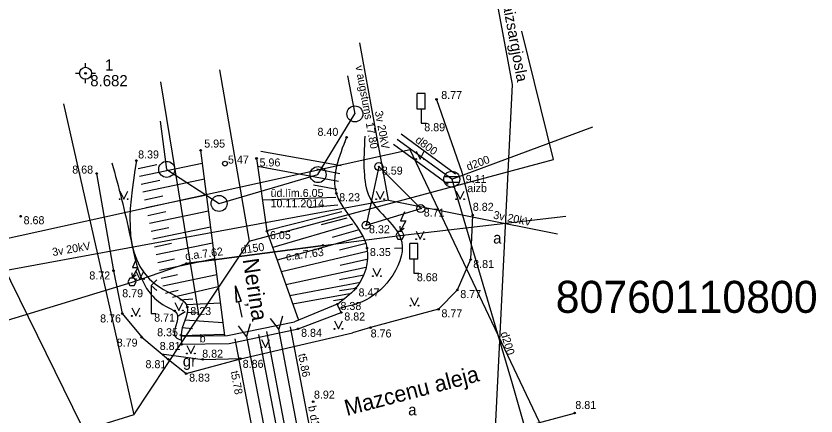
# Model space of a CAD drawing. Extents: x 496078 to 496285, y 304225 to 304369.
# Drawn here: x 496157.26 to 496207.22, y 304311.46 to 304336.44 of the extents above; entities that cross this region are included whole.
import ezdxf

# ---------------------------------------------------------------- set-up
doc = ezdxf.new("R2010")
doc.units = 0
for name, color, linetype in [('APGR_AIZS_####_####_#', 7, 'Continuous'), ('APGR_AIZS_####_TKST_#', 7, 'Continuous'), ('APGR_ELEM_####_####_#', 7, 'Continuous'), ('APGR_SARK_####_####_#', 7, 'Continuous'), ('BUVE_BDET_####_####_#', 7, 'Continuous'), ('BUVE_BDET_####_TKST_#', 7, 'Continuous'), ('CELI_CMAL_####_####_#', 7, 'Continuous'), ('CELI_CSEG_####_TKST_#', 7, 'Continuous'), ('CELI_ELEM_####_####_#', 7, 'Continuous'), ('CELI_IELA_####_TKST_#', 7, 'Continuous'), ('CKOM_ELEM_####_####_#', 7, 'Continuous'), ('ELEK_ACRL_####_####_#', 7, 'Continuous'), ('ELEK_ACRL_####_TKST_#', 7, 'Continuous'), ('ELEK_ELEM_####_####_#', 7, 'Continuous'), ('ELEK_SAVL_####_####_#', 7, 'Continuous'), ('ELEK_VADP_VSPR_####_#', 7, 'Continuous'), ('ELEK_VADV_VSPR_####_#', 7, 'Continuous'), ('ELEK_VADV_VSPR_TKST_#', 7, 'Continuous'), ('GEOD_ELEM_####_####_#', 7, 'Continuous'), ('GEOD_ELEM_####_TKST_#', 7, 'Continuous'), ('HIDG_AATZ_####_TKST_#', 7, 'Continuous'), ('HIDG_ELEM_####_####_#', 7, 'Continuous'), ('HIDG_HNOS_####_TKST_#', 7, 'Continuous'), ('HIDG_PLIN_####_####_#', 7, 'Continuous'), ('HIDG_UATZ_####_TKST_#', 7, 'Continuous'), ('HIDT_CAUR_####_####_#', 7, 'Continuous'), ('HIDT_CAUR_####_TKST_#', 7, 'Continuous'), ('HIDT_CAUR_KONT_####_#', 7, 'Continuous'), ('HIDT_ELEM_####_####_#', 7, 'Continuous'), ('Level 13', 7, 'Continuous'), ('Level 21', 7, 'Continuous'), ('Level 24', 7, 'Continuous'), ('Level 25', 7, 'Continuous'), ('Level 59', 7, 'Continuous'), ('LKAN_ELEM_####_####_#', 7, 'Continuous'), ('LKAN_ELEM_PAST_TKST_#', 7, 'Continuous'), ('LKAN_VADP_PAST_####_#', 7, 'Continuous'), ('LKAN_VADP_PAST_KONT_#', 7, 'Continuous'), ('LKAN_VADP_PAST_TKST_#', 7, 'Continuous'), ('RAMI_UZMR_####_####_#', 7, 'Continuous'), ('RELJ_AATZ_####_TKST_#', 7, 'Continuous'), ('RELJ_ELEM_####_####_#', 7, 'Continuous'), ('RELJ_HORZ_PAMT_####_#', 7, 'Continuous'), ('RELJ_NOGA_####_####_#', 7, 'Continuous'), ('TERT_ELEM_####_####_#', 7, 'Continuous')]:
    doc.layers.add(name, color=color, linetype=linetype)

msp = doc.modelspace()

# ---------------------------------------------------------------- linework, layer by layer
at = {"layer": 'APGR_AIZS_####_####_#'}
msp.add_line((496188.252, 304332.153), (496186.624, 304299.798), dxfattribs=at)
for points in [[(496186.433, 304341.916), (496188.252, 304332.153)], [(496171.482, 304276.481), (496169.303, 304289.245), (496168.626, 304293.523), (496167.995, 304297.351), (496154.713, 304324.372)]]:
    msp.add_lwpolyline(points, dxfattribs=at)
at = {"layer": 'APGR_ELEM_####_####_#'}
for centre in [(496178.42, 304330.32), (496166.67, 304326.86), (496176.12, 304326.53), (496169.94, 304324.73)]:
    msp.add_circle(centre, 0.5, dxfattribs=at)
at = {"layer": 'APGR_SARK_####_####_#'}
for p, q in [((496177.959, 304332.699), (496178.421, 304330.321)), ((496176.116, 304326.534), (496178.421, 304330.321)), ((496166.672, 304326.86), (496166.274, 304329.87)), ((496166.672, 304326.86), (496169.944, 304324.729)), ((496169.944, 304324.729), (496176.116, 304326.534))]:
    msp.add_line(p, q, dxfattribs=at)
at = {"layer": 'BUVE_BDET_####_####_#'}
for points in [[(496167.569, 304316.447), (496167.6, 304315.934), (496170.565, 304315.99), (496174.875, 304316.902), (496177.575, 304317.921), (496177.325, 304318.44), (496174.655, 304317.348)], [(496167.569, 304316.447), (496170.464, 304316.488), (496174.655, 304317.348)]]:
    msp.add_lwpolyline(points, dxfattribs=at)
at = {"layer": 'CELI_CMAL_####_####_#'}
for points in [[(496183.519, 304331.229), (496185.092, 304326.679), (496185.774, 304324.002), (496185.651, 304321.229), (496184.818, 304319.321), (496183.643, 304318.119), (496179.393, 304316.978), (496178.268, 304316.647)], [(496162.292, 304326.6), (496163.347, 304320.532), (496163.898, 304317.856), (496165.111, 304316.377), (496166.772, 304314.993), (496167.885, 304314.104), (496171.28, 304315.033), (496178.268, 304316.647)], [(496166.349, 304315.345), (496168.919, 304314.992), (496171.334, 304315.048)], [(496169.864, 304303.13), (496168.559, 304302.187), (496166.548, 304301.675), (496165.812, 304304.226), (496169.3, 304305.578), (496176.443, 304307.431), (496192.141, 304311.641)]]:
    msp.add_lwpolyline(points, dxfattribs=at)
at = {"layer": 'CELI_ELEM_####_####_#'}
for p, q in [((496182.815, 304331.588), (496182.315, 304331.588)), ((496182.315, 304330.619), (496182.315, 304331.588)), ((496182.815, 304330.619), (496182.815, 304331.588)), ((496182.815, 304330.619), (496182.315, 304330.619)), ((496182.569, 304330.619), (496182.569, 304329.741)), ((496182.569, 304329.741), (496182.884, 304329.741)), ((496182.351, 304322.221), (496181.851, 304322.221)), ((496181.851, 304321.252), (496181.851, 304322.221)), ((496182.351, 304321.252), (496182.351, 304322.221)), ((496182.351, 304321.252), (496181.851, 304321.252)), ((496182.105, 304321.252), (496182.105, 304320.374)), ((496182.105, 304320.374), (496182.42, 304320.374))]:
    msp.add_line(p, q, dxfattribs=at)
for points in [[(496166.044, 304319.96), (496165.702, 304319.604), (496166.058, 304319.305)], [(496165.702, 304319.604), (496165.702, 304317.852), (496166.001, 304317.852)]]:
    msp.add_lwpolyline(points, dxfattribs=at)
at = {"layer": 'CKOM_ELEM_####_####_#'}
for p, q in [((496181.263, 304323.039), (496181.504, 304323.178)), ((496164.53, 304320.135), (496164.771, 304320.274))]:
    msp.add_line(p, q, dxfattribs=at)
for points in [[(496181.512, 304324.201), (496181.263, 304323.638), (496181.599, 304323.638), (496181.263, 304323.039), (496181.241, 304323.309)], [(496164.779, 304321.297), (496164.53, 304320.734), (496164.866, 304320.734), (496164.53, 304320.135), (496164.508, 304320.405)]]:
    msp.add_lwpolyline(points, dxfattribs=at)
for points in [[(496181.107, 304322.509), (496181.373, 304322.509), (496181.506, 304322.739), (496181.373, 304322.97), (496181.107, 304322.97), (496180.974, 304322.739)], [(496164.374, 304319.605), (496164.64, 304319.605), (496164.773, 304319.835), (496164.64, 304320.066), (496164.374, 304320.066), (496164.241, 304319.835)]]:
    msp.add_lwpolyline(points, close=True, dxfattribs=at)
at = {"layer": 'ELEK_ACRL_####_####_#'}
msp.add_line((496176.431, 304322.113), (496167.892, 304320.979), dxfattribs=at)
at = {"layer": 'ELEK_ELEM_####_####_#'}
for centre, radius in [((496179.92, 304327.031), 0.25), ((496179.92, 304327.031), 0.0225), ((496182.535, 304324.415), 0.25), ((496182.535, 304324.415), 0.0225), ((496179.117, 304323.37), 0.25), ((496179.117, 304323.37), 0.0225)]:
    msp.add_circle(centre, radius, dxfattribs=at)
at = {"layer": 'ELEK_SAVL_####_####_#'}
for p, q in [((496179.92, 304327.031), (496179.117, 304323.37)), ((496182.535, 304324.415), (496179.92, 304327.031)), ((496179.117, 304323.37), (496182.535, 304324.415))]:
    msp.add_line(p, q, dxfattribs=at)
at = {"layer": 'ELEK_VADP_VSPR_####_#'}
msp.add_lwpolyline([(496127.411, 304308.505), (496164.51, 304319.823), (496167.892, 304320.979), (496176.431, 304322.113), (496181.231, 304322.724), (496191.596, 304323.927)], dxfattribs=at)
at = {"layer": 'ELEK_VADV_VSPR_####_#'}
for q in [(496178.731, 304334.752), (496133.06, 304316.215), (496191.07, 304322.83)]:
    msp.add_line((496180.524, 304324.939), q, dxfattribs=at)
at = {"layer": 'GEOD_ELEM_####_####_#'}
for p, q in [((496161.602, 304333.233), (496161.602, 304333.483)), ((496160.977, 304332.858), (496161.227, 304332.858)), ((496161.977, 304332.858), (496162.227, 304332.858)), ((496161.602, 304332.233), (496161.602, 304332.483))]:
    msp.add_line(p, q, dxfattribs=at)
for radius in [0.375, 0.05]:
    msp.add_circle((496161.602, 304332.858), radius, dxfattribs=at)
at = {"layer": 'HIDG_ELEM_####_####_#'}
for p, q in [((496170.958, 304319.584), (496171.312, 304318.637)), ((496171.019, 304318.574), (496170.958, 304319.584)), ((496171.312, 304318.637), (496171.019, 304318.574)), ((496171.373, 304317.627), (496171.166, 304318.605))]:
    msp.add_line(p, q, dxfattribs=at)
msp.add_lwpolyline([(496171.166, 304318.605), (496171.312, 304318.637), (496170.958, 304319.584), (496171.019, 304318.574), (496171.166, 304318.605)], dxfattribs=at)
msp.add_circle((496170.312, 304327.219), 0.15, dxfattribs=at)
at = {"layer": 'HIDG_PLIN_####_####_#'}
msp.add_line((496168.79, 304328.047), (496170.285, 304316.485), dxfattribs=at)
msp.add_lwpolyline([(496172.28, 304327.542), (496172.931, 304323.003), (496174.901, 304317.448)], dxfattribs=at)
at = {"layer": 'HIDT_CAUR_####_####_#'}
for p, q in [((496175.928, 304304.99), (496173.664, 304316.879)), ((496171.657, 304316.413), (496173.961, 304304.517))]:
    msp.add_line(p, q, dxfattribs=at)
at = {"layer": 'HIDT_CAUR_KONT_####_#'}
for p, q in [((496176.665, 304305.13), (496174.401, 304317.019)), ((496172.393, 304316.556), (496174.697, 304304.66)), ((496175.191, 304304.85), (496172.927, 304316.739)), ((496170.921, 304316.27), (496173.225, 304304.374))]:
    msp.add_line(p, q, dxfattribs=at)
at = {"layer": 'HIDT_ELEM_####_####_#'}
for points in [[(496173.891, 304317.686), (496173.664, 304316.879), (496173.154, 304317.545)], [(496171.882, 304317.22), (496171.657, 304316.413), (496171.145, 304317.078)]]:
    msp.add_lwpolyline(points, dxfattribs=at)
at = {"layer": 'Level 13'}
for points in [[(496168.698, 304317.682), (496166.302, 304332.321)], [(496171.814, 304322.383), (496168.698, 304317.682)], [(496164.622, 304311.533), (496168.698, 304317.682)]]:
    msp.add_lwpolyline(points, dxfattribs=at)
at = {"layer": 'Level 21'}
for points in [[(496160.23, 304330.947), (496164.622, 304311.533)], [(496164.622, 304311.533), (496119.806, 304297.572)]]:
    msp.add_lwpolyline(points, dxfattribs=at)
at = {"layer": 'Level 24'}
msp.add_lwpolyline([(496190.819, 304327.482), (496188.849, 304335.499)], dxfattribs=at)
at = {"layer": 'Level 25'}
for points in [[(496169.972, 304333.07), (496171.814, 304322.383)], [(496171.814, 304322.383), (496190.819, 304327.482)]]:
    msp.add_lwpolyline(points, dxfattribs=at)
at = {"layer": 'LKAN_ELEM_####_####_#'}
for p, q in [((496184.005, 304326.419), (496184.941, 304326.419)), ((496184.005, 304326.069), (496184.941, 304326.069))]:
    msp.add_line(p, q, dxfattribs=at)
msp.add_circle((496184.473, 304326.244), 0.5, dxfattribs=at)
at = {"layer": 'LKAN_VADP_PAST_####_#'}
for p, q in [((496184.473, 304326.244), (496193.289, 304329.506)), ((496184.473, 304326.244), (496181.067, 304328.727)), ((496184.473, 304326.244), (496188.241, 304313.49)), ((496188.241, 304313.49), (496191.127, 304303.418))]:
    msp.add_line(p, q, dxfattribs=at)
at = {"layer": 'LKAN_VADP_PAST_KONT_#'}
for p, q in [((496184.709, 304326.567), (496181.303, 304329.05)), ((496184.237, 304325.921), (496180.831, 304328.404))]:
    msp.add_line(p, q, dxfattribs=at)
at = {"layer": 'RAMI_UZMR_####_####_#'}
for p, q in [((496181.881, 304328.088), (496132.418, 304317.16)), ((496195.979, 304298.352), (496181.881, 304328.088))]:
    msp.add_line(p, q, dxfattribs=at)
at = {"layer": 'RELJ_ELEM_####_####_#'}
for centre in [(496183.519, 304331.229), (496177.902, 304328.862), (496168.79, 304328.047), (496164.775, 304327.411), (496172.28, 304327.542), (496162.292, 304326.6), (496177.257, 304325.369), (496157.547, 304323.934), (496185.774, 304324.002), (496172.931, 304323.003), (496176.431, 304322.113), (496179.175, 304321.947), (496167.892, 304320.979), (496185.651, 304321.229), (496163.347, 304320.532), (496178.465, 304319.425), (496184.818, 304319.321), (496177.325, 304318.44), (496163.898, 304317.856), (496167.957, 304318.262), (496177.575, 304317.921), (496183.643, 304318.119), (496174.875, 304316.902), (496179.393, 304316.978), (496165.111, 304316.377), (496167.567, 304316.504), (496167.6, 304315.934), (496166.772, 304314.993), (496168.919, 304314.992), (496171.28, 304315.033), (496167.885, 304314.104), (496175.817, 304312.355), (496192.141, 304311.641)]:
    msp.add_circle(centre, 0.05, dxfattribs=at)
at = {"layer": 'RELJ_HORZ_PAMT_####_#'}
for p, q in [((496181.386, 304321.944), (496180.886, 304321.924)), ((496167.394, 304317.719), (496167.816, 304317.987))]:
    msp.add_line(p, q, dxfattribs=at)
for points in [[(496179.04, 304328.93), (496179.001, 304326.721), (496179.338, 304325.122), (496181.35, 304322.315), (496180.598, 304319.993), (496178.868, 304318.592), (496177.45, 304318.181)], [(496163.253, 304327.267), (496164.398, 304322.639), (496165.685, 304319.058), (496166.76, 304318.23), (496167.304, 304317.851), (496167.238, 304316.372), (496167.584, 304316.191)]]:
    msp.add_spline(points, degree=3, dxfattribs=at)
at = {"layer": 'RELJ_NOGA_####_####_#'}
for p, q in [((496177.846, 304328.558), (496177.846, 304328.558)), ((496177.574, 304327.083), (496172.556, 304327.969)), ((496177.755, 304328.066), (496177.754, 304328.067)), ((496164.775, 304327.411), (496164.776, 304327.411)), ((496177.664, 304327.575), (496177.664, 304327.575)), ((496164.878, 304326.922), (496166.063, 304327.171)), ((496164.981, 304326.432), (496168.892, 304327.254)), ((496177.392, 304326.1), (496172.353, 304327.03)), ((496177.483, 304326.591), (496176.035, 304326.87)), ((496165.083, 304325.943), (496166.245, 304326.187)), ((496165.186, 304325.454), (496169.021, 304326.26)), ((496177.301, 304325.608), (496175.839, 304325.878)), ((496165.289, 304324.964), (496166.428, 304325.204)), ((496165.392, 304324.475), (496169.15, 304325.265)), ((496177.24, 304325.113), (496172.652, 304324.945)), ((496177.36, 304324.631), (496175.553, 304324.457)), ((496165.495, 304323.986), (496166.611, 304324.22)), ((496165.598, 304323.497), (496169.278, 304324.27)), ((496177.614, 304324.201), (496172.929, 304323.02)), ((496178.265, 304323.443), (496173.296, 304321.974)), ((496177.928, 304323.813), (496176.313, 304323.397)), ((496165.7, 304323.007), (496166.793, 304323.237)), ((496165.803, 304322.518), (496169.407, 304323.275)), ((496178.599, 304323.071), (496177.009, 304322.596)), ((496178.902, 304322.674), (496173.571, 304321.197)), ((496165.906, 304322.029), (496166.976, 304322.253)), ((496166.009, 304321.539), (496169.536, 304322.28)), ((496179.123, 304322.227), (496177.466, 304321.814)), ((496179.182, 304321.733), (496173.835, 304320.452)), ((496166.112, 304321.05), (496167.158, 304321.27)), ((496166.215, 304320.561), (496169.664, 304321.286)), ((496179.167, 304321.233), (496177.512, 304320.86)), ((496179.104, 304320.737), (496174.118, 304319.655)), ((496166.317, 304320.071), (496167.341, 304320.286)), ((496166.42, 304319.582), (496169.793, 304320.291)), ((496178.979, 304320.254), (496177.47, 304319.952)), ((496167.027, 304318.878), (496169.89, 304319.538)), ((496178.771, 304319.8), (496174.363, 304318.964)), ((496178.455, 304319.416), (496177.454, 304319.279)), ((496166.596, 304319.124), (496167.387, 304319.324)), ((496178.082, 304319.082), (496174.548, 304318.442)), ((496167.497, 304318.706), (496168.3, 304318.774)), ((496167.902, 304318.426), (496170.02, 304318.532)), ((496177.71, 304318.748), (496177.09, 304318.649)), ((496167.937, 304317.939), (496168.619, 304317.895)), ((496167.797, 304317.459), (496170.18, 304317.301)), ((496167.637, 304316.986), (496168.285, 304316.927)), ((496167.567, 304316.493), (496170.274, 304316.572))]:
    msp.add_line(p, q, dxfattribs=at)
for points in [[(496177.902, 304328.862), (496177.257, 304325.369), (496179.175, 304321.947), (496178.465, 304319.425), (496177.345, 304318.422), (496177.337, 304318.415)], [(496164.775, 304327.411), (496166.469, 304319.35), (496167.957, 304318.262), (496167.567, 304316.504), (496167.569, 304316.447)]]:
    msp.add_spline(points, degree=3, dxfattribs=at)
at = {"layer": 'TERT_ELEM_####_####_#'}
for p, q in [((496182.25, 304328), (496182.5, 304327.5)), ((496182.5, 304327.5), (496182.75, 304328)), ((496163.733, 304325.498), (496163.983, 304324.998)), ((496163.983, 304324.998), (496164.233, 304325.498)), ((496179.75, 304325.5), (496180, 304325)), ((496180, 304325), (496180.25, 304325.5)), ((496184.75, 304325.5), (496185, 304325)), ((496185, 304325), (496185.25, 304325.5)), ((496182.25, 304323), (496182.5, 304322.5)), ((496182.5, 304322.5), (496182.75, 304323)), ((496164.75, 304320.5), (496165, 304320)), ((496165, 304320), (496165.25, 304320.5)), ((496179.551, 304320.687), (496179.801, 304320.187)), ((496179.801, 304320.187), (496180.051, 304320.687)), ((496181.9, 304318.848), (496182.15, 304318.348)), ((496182.15, 304318.348), (496182.4, 304318.848)), ((496167.18, 304318.544), (496167.43, 304318.044)), ((496167.43, 304318.044), (496167.68, 304318.544)), ((496164.484, 304318.205), (496164.734, 304317.705)), ((496164.734, 304317.705), (496164.984, 304318.205)), ((496177.143, 304317.398), (496177.393, 304316.898)), ((496177.393, 304316.898), (496177.643, 304317.398)), ((496167.932, 304315.862), (496168.182, 304315.362)), ((496168.182, 304315.362), (496168.432, 304315.862)), ((496172.589, 304316.242), (496172.839, 304315.742)), ((496172.839, 304315.742), (496173.089, 304316.242))]:
    msp.add_line(p, q, dxfattribs=at)
for centre, radius in [((496182.25, 304327.5), 0.028), ((496182.75, 304327.5), 0.0263), ((496163.733, 304324.997), 0.028), ((496164.233, 304324.997), 0.0263), ((496179.75, 304325), 0.028), ((496180.25, 304325), 0.0263), ((496184.75, 304325), 0.028), ((496185.25, 304325), 0.0263), ((496182.25, 304322.5), 0.028), ((496182.75, 304322.5), 0.0263), ((496164.75, 304320), 0.028), ((496165.25, 304320), 0.0263), ((496179.551, 304320.187), 0.028), ((496180.051, 304320.187), 0.0263), ((496181.899, 304318.348), 0.028), ((496182.399, 304318.348), 0.0263), ((496167.179, 304318.043), 0.028), ((496167.679, 304318.043), 0.0263), ((496164.483, 304317.704), 0.028), ((496164.983, 304317.704), 0.0263), ((496177.143, 304316.897), 0.028), ((496177.643, 304316.897), 0.0263), ((496167.931, 304315.361), 0.028), ((496168.431, 304315.361), 0.0263), ((496172.588, 304315.742), 0.028), ((496173.088, 304315.742), 0.0263)]:
    msp.add_circle(centre, radius, dxfattribs=at)

# ---------------------------------------------------------------- texts
at = {"layer": 'APGR_AIZS_####_TKST_#'}
msp.add_text('ūdensteces aizsargjosla', height=0.7, rotation=280.5542, dxfattribs=at).set_placement((496186.724, 304342.1))
at = {"layer": 'BUVE_BDET_####_TKST_#'}
msp.add_text('b', height=0.5, dxfattribs=at).set_placement((496168.73, 304316.057))
at = {"layer": 'CELI_CSEG_####_TKST_#'}
for s, p in [('a', (496187.055, 304322.23)), ('gr', (496167.675, 304314.545)), ('a', (496181.749, 304311.496))]:
    msp.add_text(s, height=0.7, dxfattribs=at).set_placement(p)
at = {"layer": 'CELI_IELA_####_TKST_#'}
msp.add_text('Mazcenu aleja', height=1, rotation=14.6964, dxfattribs=at).set_placement((496177.916, 304311.459))
at = {"layer": 'ELEK_ACRL_####_TKST_#'}
for s, p in [('c.a.7.62', (496167.851, 304321.189)), ('d150', (496171.317, 304321.585)), ('c.a.7.63', (496174.143, 304321.153))]:
    msp.add_text(s, height=0.5, rotation=7.5648, dxfattribs=at).set_placement(p)
at = {"layer": 'ELEK_VADV_VSPR_TKST_#'}
for s, rotation, p in [('v augstums 17.80', 280.3528, (496178.451, 304333.302)), ('3v 20kV', 280.3528, (496179.665, 304330.473)), ('3v 20kV', 348.6927, (496187.035, 304323.79)), ('3v 20kV', 9.8639, (496159.563, 304321.44))]:
    msp.add_text(s, height=0.5, rotation=rotation, dxfattribs=at).set_placement(p)
at = {"layer": 'GEOD_ELEM_####_TKST_#'}
for s, p in [(' 1', (496162.559, 304333.031)), (' 8.682', (496161.633, 304332.048))]:
    msp.add_text(s, height=0.7, dxfattribs=at).set_placement(p)
at = {"layer": 'HIDG_AATZ_####_TKST_#'}
msp.add_text(' 5.47', height=0.5, dxfattribs=at).set_placement((496170.312, 304327.219))
at = {"layer": 'HIDG_HNOS_####_TKST_#'}
msp.add_text('Neriņa', height=1, rotation=278.6471, dxfattribs=at).set_placement((496171.415, 304321.231))
at = {"layer": 'HIDG_UATZ_####_TKST_#'}
for s, p in [('ūd.līm.6.05', (496173.156, 304325.137)), ('10.11.2014', (496173.156, 304324.487))]:
    msp.add_text(s, height=0.5, dxfattribs=at).set_placement(p)
at = {"layer": 'HIDT_CAUR_####_TKST_#'}
for s, rotation, p in [('t5.86', 280.7816, (496174.879, 304315.309)), ('t5.78', 280.9613, (496170.655, 304314.223)), ('b d1500', 280.7816, (496175.499, 304312.055))]:
    msp.add_text(s, height=0.5, rotation=rotation, dxfattribs=at).set_placement(p)
at = {"layer": 'Level 59'}
msp.add_text('80760110800', height=2, dxfattribs=at).set_placement((496190.961, 304317.899))
at = {"layer": 'LKAN_ELEM_PAST_TKST_#'}
for s, p in [('9.11', (496185.338, 304326.01)), ('aizb', (496185.442, 304325.437))]:
    msp.add_text(s, height=0.5, dxfattribs=at).set_placement(p)
at = {"layer": 'LKAN_VADP_PAST_TKST_#'}
for s, rotation, p in [('d800', 323.6536, (496182.149, 304328.595)), ('d200', 20.2198, (496185.494, 304326.769)), ('d200', 286.7872, (496187.513, 304316.643))]:
    msp.add_text(s, height=0.5, rotation=rotation, dxfattribs=at).set_placement(p)
at = {"layer": 'RELJ_AATZ_####_TKST_#'}
for s, p in [(' 8.77', (496183.628, 304331.252)), (' 8.40', (496175.901, 304328.953)), (' 8.89', (496182.569, 304329.241)), (' 5.95', (496168.828, 304328.221)), (' 8.39', (496164.699, 304327.541)), (' 5.96', (496172.28, 304327.042)), (' 8.68', (496160.586, 304326.596)), (' 8.59', (496179.92, 304326.531)), (' 8.23', (496177.257, 304324.869)), (' 8.71', (496182.535, 304323.915)), (' 8.82', (496185.6, 304324.27)), (' 8.68', (496157.547, 304323.434)), (' 8.32', (496179.117, 304322.87)), (' 6.05', (496172.931, 304322.503)), (' 8.35', (496179.175, 304321.447)), (' 8.81', (496185.624, 304320.698)), (' 8.72', (496161.651, 304319.984)), (' 8.68', (496182.105, 304319.874)), (' 8.79', (496163.706, 304318.874)), (' 8.47', (496178.465, 304318.925)), (' 8.77', (496184.818, 304318.821)), (' 8.38', (496177.336, 304318.081)), (' 8.71', (496165.702, 304317.352)), (' 8.23', (496167.957, 304317.762)), (' 8.82', (496177.575, 304317.421)), (' 8.77', (496183.643, 304317.619)), (' 8.76', (496162.326, 304317.299)), (' 8.35', (496165.888, 304316.439)), (' 8.84', (496174.875, 304316.402)), (' 8.76', (496179.219, 304316.364)), (' 8.79', (496163.363, 304315.79)), (' 8.81', (496166.048, 304315.581)), (' 8.82', (496168.701, 304315.102)), (' 8.81', (496165.16, 304314.444)), (' 8.86', (496171.23, 304314.464)), (' 8.83', (496167.885, 304313.604)), (' 8.92', (496175.679, 304312.543)), (' 8.81', (496192.003, 304311.895))]:
    msp.add_text(s, height=0.5, dxfattribs=at).set_placement(p)

doc.saveas('drawing.dxf')
